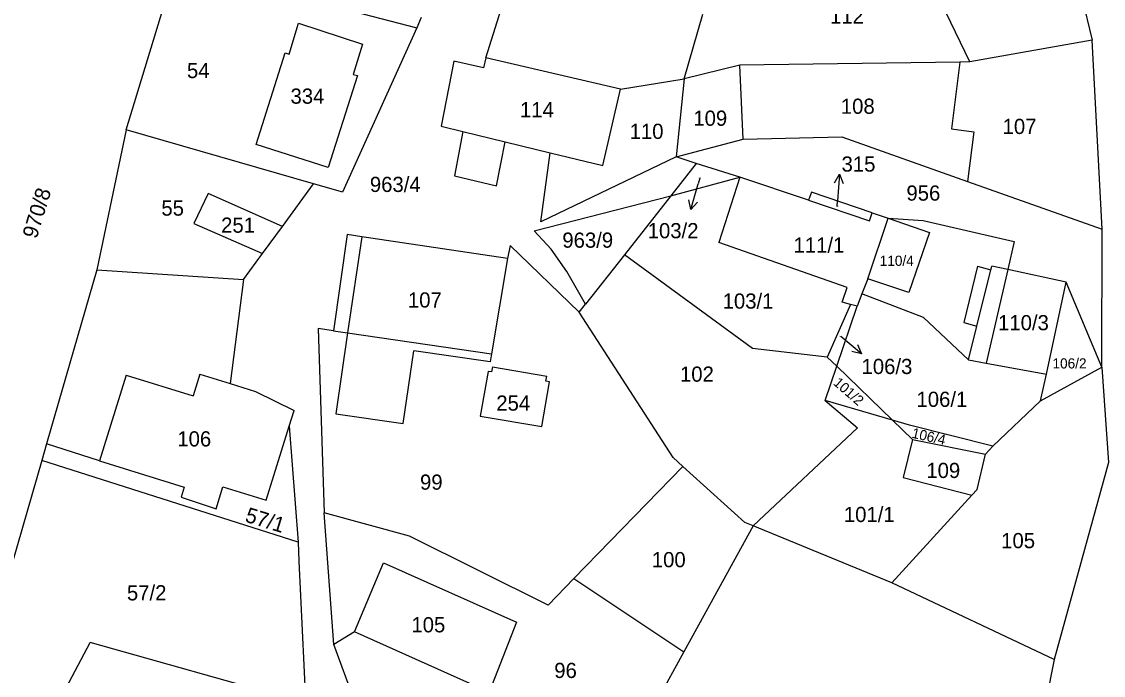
# Model space of a CAD drawing. Extents: x -593358 to -590116, y -1072518 to -1068420.
# Drawn here: x -591702.6 to -591581.5, y -1070557.8 to -1070484.6 of the extents above; entities that cross this region are included whole.
import ezdxf

# ---------------------------------------------------------------- set-up
doc = ezdxf.new("R2010")
doc.units = 0
for name, color, linetype in [('Parcela KN', 7, 'Continuous'), ('Parcelní číslo', 7, 'Continuous'), ('Parcelní číslo_stavební', 7, 'Continuous'), ('stavby - vnitřní kresba', 7, 'Continuous'), ('Vrstva 16', 7, 'Continuous')]:
    doc.layers.add(name, color=color, linetype=linetype)

msp = doc.modelspace()

# ---------------------------------------------------------------- linework, layer by layer
at = {"layer": 'Parcela KN'}
for p, q in [((-591586.69, -1070470.35), (-591582.74, -1070486.67)), ((-591650.64, -1070488.64), (-591646.36, -1070474.98)), ((-591690.92, -1070496.7), (-591685.28, -1070478.23)), ((-591685.28, -1070478.23), (-591658.37, -1070485.29)), ((-591657.87, -1070484.12), (-591658.37, -1070485.29)), ((-591628.41, -1070490.99), (-591626.35, -1070483.75)), ((-591596.43, -1070489.09), (-591599.09, -1070483.58)), ((-591672.64, -1070488.21), (-591671.6, -1070484.76)), ((-591671.6, -1070484.76), (-591664.43, -1070487.09)), ((-591658.37, -1070485.29), (-591666.7, -1070503.67)), ((-591582.74, -1070486.67), (-591596.43, -1070489.09)), ((-591581.63, -1070507.81), (-591582.74, -1070486.67)), ((-591676.37, -1070498.34), (-591673.12, -1070488.06)), ((-591673.12, -1070488.06), (-591672.64, -1070488.21)), ((-591664.43, -1070487.09), (-591665.51, -1070490.49)), ((-591654.22, -1070488.99), (-591655.64, -1070496.3)), ((-591650.9, -1070489.76), (-591654.22, -1070488.99)), ((-591650.64, -1070488.64), (-591650.9, -1070489.76)), ((-591635.54, -1070492.14), (-591650.64, -1070488.64)), ((-591597.57, -1070489.11), (-591622.21, -1070489.44)), ((-591597.57, -1070489.11), (-591598.5, -1070496.58)), ((-591596.43, -1070489.09), (-591597.57, -1070489.11)), ((-591665.51, -1070490.49), (-591665.02, -1070490.61)), ((-591622.21, -1070489.44), (-591628.41, -1070490.99)), ((-591621.83, -1070497.73), (-591622.21, -1070489.44)), ((-591665.02, -1070490.61), (-591668.28, -1070500.9)), ((-591635.54, -1070492.14), (-591628.41, -1070490.99)), ((-591628.41, -1070490.99), (-591629.31, -1070499.72)), ((-591637.52, -1070500.7), (-591635.54, -1070492.14)), ((-591655.64, -1070496.3), (-591653.2, -1070496.89)), ((-591598.5, -1070496.58), (-591596, -1070496.92)), ((-591690.92, -1070496.7), (-591694.21, -1070512.35)), ((-591669.93, -1070502.74), (-591690.92, -1070496.7)), ((-591653.2, -1070496.89), (-591654.15, -1070501.83)), ((-591629.31, -1070499.72), (-591621.83, -1070497.73)), ((-591621.83, -1070497.73), (-591610.77, -1070497.46)), ((-591610.77, -1070497.46), (-591596.69, -1070502.46)), ((-591596, -1070496.92), (-591596.69, -1070502.46)), ((-591668.28, -1070500.9), (-591676.37, -1070498.34)), ((-591649.45, -1070502.95), (-591648.49, -1070498.04)), ((-591648.49, -1070498.04), (-591643.44, -1070499.27)), ((-591644.47, -1070507), (-591643.44, -1070499.27)), ((-591629.31, -1070499.72), (-591644.47, -1070507)), ((-591643.44, -1070499.27), (-591637.52, -1070500.7)), ((-591627.07, -1070500.48), (-591629.31, -1070499.72)), ((-591627.07, -1070500.48), (-591629.91, -1070504.08)), ((-591622.18, -1070501.99), (-591627.07, -1070500.48)), ((-591654.15, -1070501.83), (-591649.45, -1070502.95)), ((-591629.91, -1070504.08), (-591622.18, -1070501.99)), ((-591622.18, -1070501.99), (-591624.54, -1070509.31)), ((-591614.49, -1070504.56), (-591622.18, -1070501.99)), ((-591596.69, -1070502.46), (-591581.63, -1070507.81)), ((-591681.72, -1070503.83), (-591683.33, -1070507.19)), ((-591673.42, -1070507.52), (-591681.72, -1070503.83)), ((-591673.42, -1070507.52), (-591669.93, -1070502.74)), ((-591667.18, -1070503.53), (-591669.93, -1070502.74)), ((-591666.7, -1070503.67), (-591667.18, -1070503.53)), ((-591614.18, -1070503.66), (-591614.49, -1070504.56)), ((-591607.36, -1070505.97), (-591614.18, -1070503.66)), ((-591645.23, -1070508.01), (-591629.91, -1070504.08)), ((-591629.91, -1070504.08), (-591635.1, -1070510.67)), ((-591614.49, -1070504.56), (-591607.66, -1070506.87)), ((-591607.66, -1070506.87), (-591607.36, -1070505.97)), ((-591607.36, -1070505.97), (-591605.57, -1070506.6)), ((-591683.33, -1070507.19), (-591675.63, -1070510.54)), ((-591607.86, -1070513.38), (-591605.57, -1070506.6)), ((-591605.57, -1070506.6), (-591600.96, -1070508.19)), ((-591605.57, -1070506.6), (-591601.67, -1070506.86)), ((-591601.67, -1070506.86), (-591591.47, -1070509.18)), ((-591675.63, -1070510.54), (-591673.42, -1070507.52)), ((-591666.15, -1070508.42), (-591667.71, -1070519.18)), ((-591664.51, -1070508.66), (-591666.15, -1070508.42)), ((-591648.21, -1070511.09), (-591664.51, -1070508.66)), ((-591643.32, -1070510.06), (-591645.23, -1070508.01)), ((-591600.96, -1070508.19), (-591603.28, -1070514.92)), ((-591581.67, -1070523.28), (-591581.63, -1070507.81)), ((-591647.93, -1070509.66), (-591648.21, -1070511.09)), ((-591640.18, -1070517.11), (-591647.93, -1070509.66)), ((-591610.19, -1070514.34), (-591624.54, -1070509.31)), ((-591591.47, -1070509.18), (-591592.2, -1070512.34)), ((-591677.76, -1070513.46), (-591675.63, -1070510.54)), ((-591648.21, -1070511.09), (-591650.01, -1070521.77)), ((-591641.55, -1070512.54), (-591643.32, -1070510.06)), ((-591635.1, -1070510.67), (-591639.47, -1070516.2)), ((-591620.79, -1070521.16), (-591635.1, -1070510.67)), ((-591694.21, -1070512.35), (-591699.84, -1070531.86)), ((-591694.21, -1070512.35), (-591677.76, -1070513.46)), ((-591585.65, -1070513.76), (-591592.2, -1070512.34)), ((-591677.76, -1070513.46), (-591679.27, -1070525.09)), ((-591639.47, -1070516.2), (-591641.55, -1070512.54)), ((-591607.86, -1070513.38), (-591608.52, -1070515.06)), ((-591603.28, -1070514.92), (-591607.86, -1070513.38)), ((-591610.74, -1070515.97), (-591610.19, -1070514.34)), ((-591587.87, -1070524.03), (-591585.65, -1070513.76)), ((-591581.67, -1070523.28), (-591585.65, -1070513.76)), ((-591609.79, -1070516.23), (-591610.74, -1070515.97)), ((-591608.52, -1070515.06), (-591609.06, -1070516.43)), ((-591601.63, -1070517.7), (-591608.52, -1070515.06)), ((-591640.18, -1070517.11), (-591639.47, -1070516.2)), ((-591629.67, -1070533.38), (-591640.18, -1070517.11)), ((-591609.79, -1070516.23), (-591612.4, -1070522.13)), ((-591611.34, -1070523.16), (-591609.06, -1070516.43)), ((-591609.06, -1070516.43), (-591609.79, -1070516.23)), ((-591596.6, -1070522.43), (-591601.63, -1070517.7)), ((-591667.71, -1070519.18), (-591669.4, -1070518.93)), ((-591669.4, -1070518.93), (-591668.73, -1070539.56)), ((-591667.71, -1070519.18), (-591666.13, -1070519.41)), ((-591666.13, -1070519.41), (-591667.42, -1070528.47)), ((-591659.89, -1070529.56), (-591658.71, -1070521.45)), ((-591650.15, -1070522.68), (-591658.71, -1070521.45)), ((-591650.01, -1070521.77), (-591650.15, -1070522.68)), ((-591612.4, -1070522.13), (-591620.79, -1070521.16)), ((-591649.89, -1070523.23), (-591649.99, -1070523.8)), ((-591649.89, -1070523.23), (-591643.81, -1070524.27)), ((-591612.63, -1070526.98), (-591611.34, -1070523.16)), ((-591612.4, -1070522.13), (-591611.34, -1070523.16)), ((-591611.34, -1070523.16), (-591605.1, -1070529.2)), ((-591596.6, -1070522.43), (-591594.61, -1070522.82)), ((-591594.61, -1070522.82), (-591587.87, -1070524.03)), ((-591650.38, -1070523.73), (-591651.27, -1070528.73)), ((-591649.99, -1070523.8), (-591650.38, -1070523.73)), ((-591643.91, -1070524.84), (-591643.81, -1070524.27)), ((-591588.52, -1070527.04), (-591581.67, -1070523.28)), ((-591588.52, -1070527.04), (-591587.87, -1070524.03)), ((-591581.67, -1070523.28), (-591580.91, -1070533.95)), ((-591679.27, -1070525.09), (-591676.44, -1070525.97)), ((-591644.37, -1070529.89), (-591643.51, -1070524.91)), ((-591643.51, -1070524.91), (-591643.91, -1070524.84)), ((-591676.44, -1070525.97), (-591672.1, -1070528.11)), ((-591605.1, -1070529.2), (-591612.63, -1070526.98)), ((-591612.63, -1070526.98), (-591609.02, -1070530.06)), ((-591593.86, -1070532.12), (-591588.52, -1070527.04)), ((-591672.64, -1070529.85), (-591672.1, -1070528.11)), ((-591667.42, -1070528.47), (-591659.89, -1070529.56)), ((-591651.27, -1070528.73), (-591644.37, -1070529.89)), ((-591603.2, -1070529.76), (-591605.1, -1070529.2)), ((-591605.1, -1070529.2), (-591602.85, -1070531.37)), ((-591675.22, -1070538.16), (-591672.64, -1070529.85)), ((-591672.64, -1070529.85), (-591671.66, -1070542.85)), ((-591609.02, -1070530.06), (-591620.72, -1070541.04)), ((-591593.86, -1070532.12), (-591603.2, -1070529.76)), ((-591602.85, -1070531.37), (-591603.89, -1070535.61)), ((-591602.85, -1070531.37), (-591594.67, -1070533.02)), ((-591699.84, -1070531.86), (-591700.37, -1070533.71)), ((-591693.9, -1070533.74), (-591699.84, -1070531.86)), ((-591594.67, -1070533.02), (-591593.86, -1070532.12)), ((-591700.37, -1070533.71), (-591709.96, -1070566.95)), ((-591671.66, -1070542.85), (-591700.37, -1070533.71)), ((-591693.9, -1070533.74), (-591684.41, -1070536.69)), ((-591628.58, -1070534.38), (-591629.67, -1070533.38)), ((-591595.63, -1070536.94), (-591594.67, -1070533.02)), ((-591580.91, -1070533.95), (-591587, -1070555.98)), ((-591628.58, -1070534.38), (-591640.77, -1070546.91)), ((-591621.64, -1070540.67), (-591628.58, -1070534.38)), ((-591603.89, -1070535.61), (-591596.22, -1070537.59)), ((-591684.41, -1070536.69), (-591684.76, -1070537.82)), ((-591680.83, -1070539.11), (-591680.07, -1070536.65)), ((-591680.07, -1070536.65), (-591675.22, -1070538.16)), ((-591605.19, -1070547.42), (-591596.22, -1070537.59)), ((-591596.22, -1070537.59), (-591595.63, -1070536.94)), ((-591684.76, -1070537.82), (-591680.83, -1070539.11)), ((-591659.19, -1070542.18), (-591668.73, -1070539.56)), ((-591667.67, -1070554.3), (-591668.73, -1070539.56)), ((-591620.72, -1070541.04), (-591628.45, -1070555.12)), ((-591620.72, -1070541.04), (-591621.64, -1070540.67)), ((-591605.19, -1070547.42), (-591620.72, -1070541.04)), ((-591643.66, -1070549.89), (-591659.19, -1070542.18)), ((-591671.66, -1070542.85), (-591671.59, -1070544.97)), ((-591671.59, -1070544.97), (-591670.83, -1070560.85)), ((-591665.33, -1070552.91), (-591662.1, -1070545.17)), ((-591662.1, -1070545.17), (-591647.2, -1070551.82)), ((-591640.77, -1070546.91), (-591643.66, -1070549.89)), ((-591640.77, -1070546.91), (-591628.45, -1070555.12)), ((-591587, -1070555.98), (-591605.19, -1070547.42)), ((-591647.2, -1070551.82), (-591650.26, -1070559.63)), ((-591665.33, -1070552.91), (-591667.67, -1070554.3)), ((-591697.64, -1070559.15), (-591694.95, -1070554.09)), ((-591670.83, -1070560.85), (-591694.95, -1070554.09)), ((-591661.85, -1070569.94), (-591667.67, -1070554.3)), ((-591628.45, -1070555.12), (-591633.68, -1070564.64)), ((-591587, -1070555.98), (-591591.64, -1070579.17))]:
    msp.add_line(p, q, dxfattribs=at)
at = {"layer": 'stavby - vnitřní kresba'}
for p, q in [((-591653.2, -1070496.89), (-591648.49, -1070498.04)), ((-591664.51, -1070508.66), (-591666.13, -1070519.41)), ((-591595.57, -1070511.95), (-591597.13, -1070518.27)), ((-591595.67, -1070518.69), (-591594.09, -1070512.35)), ((-591595.57, -1070511.95), (-591594.09, -1070512.35)), ((-591592.2, -1070512.34), (-591594.61, -1070522.82)), ((-591594.09, -1070512.35), (-591593.99, -1070511.94)), ((-591592.2, -1070512.34), (-591593.99, -1070511.94)), ((-591597.13, -1070518.27), (-591595.67, -1070518.69)), ((-591666.13, -1070519.41), (-591650.01, -1070521.77)), ((-591596.6, -1070522.43), (-591595.67, -1070518.69)), ((-591690.9, -1070524.16), (-591693.9, -1070533.74)), ((-591690.9, -1070524.16), (-591683.41, -1070526.49)), ((-591682.65, -1070524.05), (-591683.41, -1070526.49)), ((-591682.65, -1070524.05), (-591679.27, -1070525.09)), ((-591650.26, -1070559.63), (-591665.33, -1070552.91))]:
    msp.add_line(p, q, dxfattribs=at)
at = {"layer": 'Vrstva 16'}
for p, q in [((-591626.66, -1070502.1), (-591626.85, -1070502.74)), ((-591611.043, -1070501.657), (-591611.25, -1070504.65)), ((-591627.692, -1070505.619), (-591626.85, -1070502.74)), ((-591611.29, -1070505.29), (-591611.25, -1070504.65)), ((-591610.89, -1070519.81), (-591610.87, -1070519.83)), ((-591608.574, -1070521.761), (-591610.87, -1070519.83))]:
    msp.add_line(p, q, dxfattribs=at)
for points in [[(-591611.611, -1070502.62), (-591611.043, -1070501.657), (-591610.613, -1070502.689)], [(-591626.932, -1070504.8), (-591627.692, -1070505.619), (-591627.891, -1070504.519)], [(-591609.018, -1070520.735), (-591608.574, -1070521.761), (-591609.661, -1070521.5)]]:
    msp.add_lwpolyline(points, dxfattribs=at)

# ---------------------------------------------------------------- texts
at = {"layer": 'Parcelní číslo'}
for s, height, p in [('112', 1.7, (-591612.092, -1070484.79)), ('54', 1.7, (-591684.102, -1070490.9)), ('108', 1.7, (-591610.883, -1070494.9)), ('109', 1.7, (-591627.403, -1070496.24)), ('110', 1.7, (-591634.535, -1070497.71)), ('107', 1.7, (-591592.773, -1070497.16)), ('963/4', 1.7, (-591663.62, -1070503.65)), ('956', 1.7, (-591603.541, -1070504.62)), ('55', 1.7, (-591686.969, -1070506.3)), ('963/9', 1.7, (-591642.07, -1070509.89)), ('103/1', 1.7, (-591624.121, -1070516.71)), ('106/3', 0.1, (-591611.078, -1070519.83)), ('102', 1.7, (-591628.897, -1070524.89)), ('106/2', 1.14, (-591587.186, -1070523.41)), ('106/1', 1.7, (-591602.414, -1070527.71)), ('99', 1.7, (-591658.005, -1070536.98)), ('101/1', 1.7, (-591610.546, -1070540.6)), ('105', 1.7, (-591592.93, -1070543.53)), ('100', 1.7, (-591632.05, -1070545.66)), ('57/2', 1.7, (-591690.824, -1070549.37)), ('96', 1.7, (-591642.975, -1070558.06))]:
    msp.add_text(s, height=height, dxfattribs=at).set_placement(p)
for s, height, rotation, p in [('103/2', 0.1, 14.72502, (-591626.846, -1070502.149)), ('970/8', 1.7, 73.10941, (-591700.939, -1070508.961)), ('101/2', 1.14, 318.79372, (-591611.812, -1070525.146)), ('106/4', 1.14, 347.21243, (-591603.015, -1070531.148)), ('57/1', 1.7, 342.91524, (-591677.697, -1070540.534))]:
    msp.add_text(s, height=height, rotation=rotation, dxfattribs=at).set_placement(p)
at = {"layer": 'Parcelní číslo_stavební'}
for s, height, p in [('334', 1.7, (-591672.508, -1070493.77)), ('114', 1.7, (-591646.818, -1070495.29)), ('315', 0.1, (-591611.392, -1070505.29)), ('251', 1.7, (-591680.277, -1070508.21)), ('111/1', 1.7, (-591616.181, -1070510.44)), ('110/4', 1.14, (-591606.533, -1070511.92)), ('107', 1.7, (-591659.363, -1070516.59)), ('110/3', 1.7, (-591593.281, -1070519.13)), ('254', 1.7, (-591649.465, -1070528.13)), ('106', 1.7, (-591685.183, -1070532.14)), ('109', 1.7, (-591601.313, -1070535.67)), ('105', 1.7, (-591658.97, -1070552.95))]:
    msp.add_text(s, height=height, dxfattribs=at).set_placement(p)
at = {"layer": 'Vrstva 16'}
for s, p in [('315', (-591610.803, -1070501.37)), ('103/2', (-591632.513, -1070508.83)), ('106/3', (-591608.567, -1070524.03))]:
    msp.add_text(s, height=1.7, dxfattribs=at).set_placement(p)

doc.saveas('drawing.dxf')
